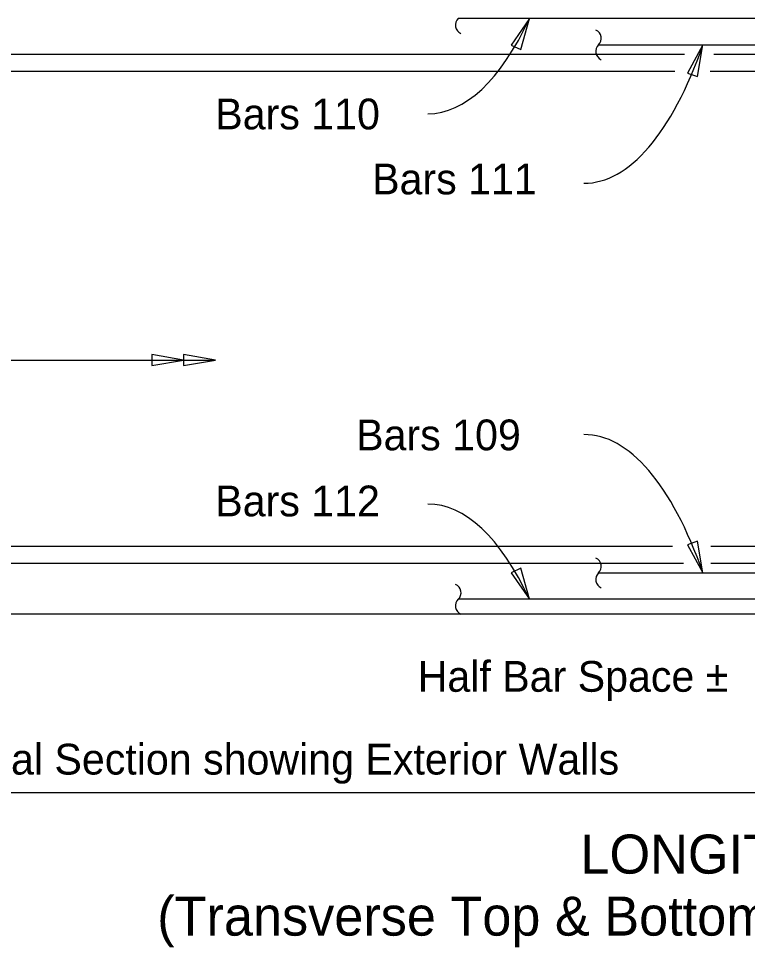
# Model space of a CAD drawing. Extents: x 0 to 221, y -2 to 90.
# Drawn here: x 40.19 to 54.52, y 7.04 to 25.31 of the extents above; entities that cross this region are included whole.
import ezdxf

# ---------------------------------------------------------------- set-up
doc = ezdxf.new("R2010")
doc.units = 0
for name, color, linetype in [('AdhocPoint_dp', 7, 'Continuous'), ('Leader', 7, 'Continuous'), ('PlotBorder_dp', 7, 'Continuous'), ('Rebar', 7, 'Continuous'), ('WallConc', 7, 'Continuous'), ('WallConc_h', 7, 'Continuous')]:
    doc.layers.add(name, color=color, linetype=linetype)

msp = doc.modelspace()

# ---------------------------------------------------------------- linework, layer by layer
at = {"layer": 'Leader'}
for centre, major_axis, start_param, end_param in [((48.303, 31.773), (0.059, 8.337), 3.141593, 3.827332), ((51.37, 30.406), (0.059, 8.337), 3.141593, 3.975964), ((51.37, 8.79), (0.059, -8.337), 2.307221, 3.141593), ((48.303, 7.423), (0.059, -8.337), 2.455853, 3.141593)]:
    msp.add_ellipse(centre, major_axis=major_axis, ratio=0.375478, start_param=start_param, end_param=end_param, dxfattribs=at)
at = {"layer": 'PlotBorder_dp'}
for p, q in [((26.315, 18.592), (44.064, 18.592)), ((36.523, 10.087), (57.267, 10.087))]:
    msp.add_line(p, q, dxfattribs=at)
for points in [[(50.24, 25.306), (49.879, 24.785), (50.071, 24.695)], [(53.65, 24.79), (53.344, 24.234), (53.544, 24.165)], [(43.439, 18.592), (42.814, 18.698), (42.814, 18.486)], [(44.064, 18.592), (43.439, 18.698), (43.439, 18.486)], [(53.65, 14.406), (53.544, 15.031), (53.344, 14.961)], [(50.24, 13.89), (50.071, 14.5), (49.879, 14.411)]]:
    msp.add_lwpolyline(points, close=True, dxfattribs=at)
for centre, start, end in [((48.964, 25.178), 134.1793, 245.9065), ((51.472, 24.918), 314.1793, 65.9065), ((51.722, 24.661), 134.1793, 245.9065), ((51.472, 14.535), 314.1793, 65.9065), ((51.722, 14.278), 134.1793, 245.9065), ((48.715, 14.018), 314.1793, 65.9065), ((48.964, 13.761), 134.1793, 245.9065)]:
    msp.add_arc(centre, 0.179, start, end, dxfattribs=at)
at = {"layer": 'Rebar'}
for p, q in [((56.892, 25.306), (48.839, 25.306)), ((51.597, 24.79), (61.826, 24.79)), ((51.597, 14.406), (61.826, 14.406)), ((57.01, 13.89), (48.839, 13.89))]:
    msp.add_line(p, q, dxfattribs=at)
at = {"layer": 'WallConc'}
for p, q in [((53.285, 24.598), (26.415, 24.598)), ((65.695, 24.598), (53.866, 24.598)), ((24.478, 14.598), (53.269, 14.598)), ((53.808, 14.598), (65.695, 14.598)), ((56.966, 13.598), (25.415, 13.598))]:
    msp.add_line(p, q, dxfattribs=at)
at = {"layer": 'WallConc_h'}
for p, q in [((53.095, 24.265), (25.915, 24.265)), ((65.695, 24.265), (53.792, 24.265)), ((25.915, 14.931), (53.052, 14.931)), ((53.808, 14.931), (65.695, 14.931))]:
    msp.add_line(p, q, dxfattribs=at)

# ---------------------------------------------------------------- texts
at = {"layer": 'AdhocPoint_dp'}
for s, height, p in [('Bars 110', 0.6048, (44.062, 23.128)), ('Bars 111', 0.6048, (47.146, 21.85)), ('Bars 109', 0.6048, (46.832, 16.818)), ('Bars 112', 0.6048, (44.062, 15.519)), ('Half Bar Space ±', 0.6048, (48.041, 12.07)), ('Partial Section showing Exterior Walls', 0.6048, (38.383, 10.442)), ('LONGITUDINAL SECTION THRU CULVERT', 0.768, (51.242, 8.494)), ('(Transverse Top & Bottom Slab Reinforcing Not Shown For Clarity)', 0.768, (42.921, 7.275))]:
    msp.add_text(s, height=height, dxfattribs=at).set_placement(p)

doc.saveas('drawing.dxf')
